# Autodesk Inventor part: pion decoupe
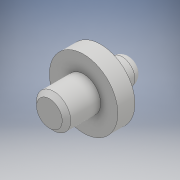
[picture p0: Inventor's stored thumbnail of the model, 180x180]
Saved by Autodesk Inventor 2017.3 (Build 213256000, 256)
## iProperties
Part Number: pion decoupe
Material: Générique
Document SubType Name: Modeling
Designer: ficho
Density: 1 g/cm^3
Appearance: Par défaut
Author: ficho
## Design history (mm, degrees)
sketch "Esquisse1"
  geometry: L1 (4, 0)-(4, -8); L2 (4, -8)-(0, -8); L3 (0, -8)-(0, 0); L4 (4, 0)-(8, 0); L5 (8, 0)-(8, 4); L6 (8, 4)-(3, 4); L7 (0, 4)-(0, 0); L8 (3, 4)-(3, 9); L9 (1, 11)-(0, 11); L10 (0, 11)-(0, 4); A1 r 2 centre (1, 9) between (3, 9) and (1, 11)
  constraints: 20 end point, 4 parallel, 2 point on circle, 2 tangent, 1 centre point, 1 horizontal, 1 perpendicular
  dimensions: "d0" = 4 distance between parallel lines of L1 L3; "d3" = 8 distance between parallel lines of L5 L7; "d4" = 3 distance between parallel lines of L8 L10; "d5" = 7 distance between parallel lines of L6 L9; "d6" = 2 radius of A1 (derived)
revolve "Révolution1" sketch "Esquisse1" stored, may be unused: angle "d7" = 90 deg
chamfer "Chanfrein1" distance "d8" = 1; stored, may be unused: second distance "d9" = 2, angle "d10" = 45 deg
node "Solide1"
